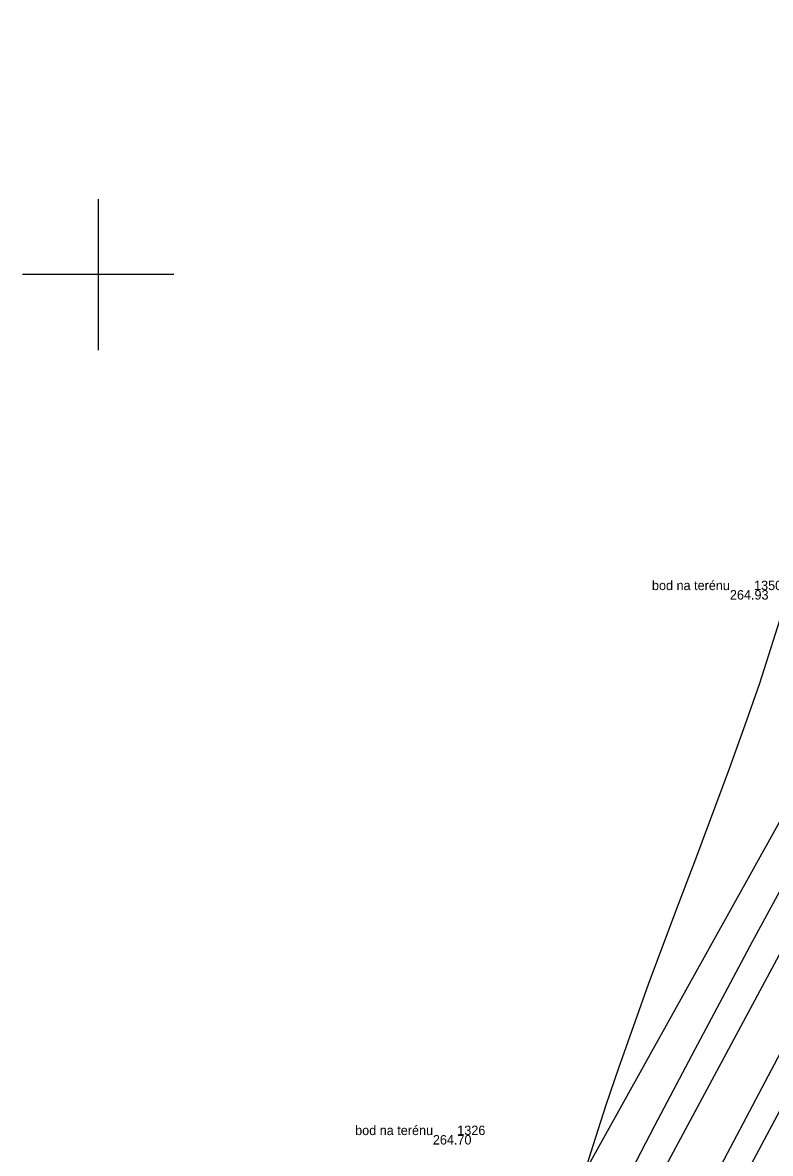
# Model space of a CAD drawing. Extents: x -567962 to -566460, y -1093720 to -1089838.
# Drawn here: x -567204 to -567164.4, y -1090846.6 to -1090786.7 of the extents above; entities that cross this region are included whole.
import ezdxf

# ---------------------------------------------------------------- set-up
doc = ezdxf.new("R2010")
doc.units = 0
for name, color, linetype in [('0_osa hráze', 7, 'Continuous'), ('bod_znacka', 7, 'Continuous'), ('cislo_bodu', 7, 'Continuous'), ('ctvercova_sit', 7, 'Continuous'), ('hlavni_vrst', 7, 'Continuous'), ('hrana_L', 7, 'Continuous'), ('kod_bodu', 7, 'Continuous'), ('norm_vrst', 7, 'Continuous'), ('vyska_bodu', 7, 'Continuous')]:
    doc.layers.add(name, color=color, linetype=linetype)

msp = doc.modelspace()

# ---------------------------------------------------------------- linework, layer by layer
at = {"layer": '0_osa hráze'}
msp.add_lwpolyline([(-567089.84, -1090700.38), (-567096.414, -1090713.39), (-567177.884, -1090867.779)], dxfattribs=at)
at = {"layer": 'bod_znacka'}
for p, q in [((-567165.26, -1090816.72), (-567165.26, -1090816.72)), ((-567180.98, -1090845.59), (-567180.98, -1090845.59))]:
    msp.add_line(p, q, dxfattribs=at)
at = {"layer": 'ctvercova_sit'}
for points in [[(-567200, -1090796), (-567200, -1090804)], [(-567196, -1090800), (-567204, -1090800)]]:
    msp.add_lwpolyline(points, dxfattribs=at)
at = {"layer": 'hlavni_vrst'}
msp.add_lwpolyline([(-567162.493, -1090812.221), (-567162.528, -1090812.45), (-567163.012, -1090814.932), (-567163.353, -1090816.337), (-567163.66, -1090817.553), (-567164.977, -1090821.675), (-567165.662, -1090823.624), (-567166.58, -1090826.191), (-567167.297, -1090828.123), (-567168.37, -1090830.969), (-567169.425, -1090833.739), (-567170.866, -1090837.606), (-567171.566, -1090839.547), (-567172.449, -1090842.05), (-567173.114, -1090844.011), (-567173.801, -1090846.164), (-567174.216, -1090847.494)], dxfattribs=at)
at = {"layer": 'hrana_L'}
for p, q in [((-567159.04, -1090820.21), (-567174.87, -1090848.67)), ((-567156.18, -1090821.59), (-567171.65, -1090850.41)), ((-567168.28, -1090852.53), (-567152.75, -1090823.34))]:
    msp.add_line(p, q, dxfattribs=at)
at = {"layer": 'norm_vrst'}
msp.add_lwpolyline([(-567162.51, -1090830.095), (-567165.357, -1090835.349), (-567168.398, -1090841.051), (-567170.527, -1090845.095), (-567172.703, -1090849.28)], dxfattribs=at)

# ---------------------------------------------------------------- texts
at = {"layer": 'cislo_bodu'}
for s, p in [('1350', (-567165.26, -1090816.72)), ('1326', (-567180.98, -1090845.59))]:
    msp.add_text(s, height=0.5, dxfattribs=at).set_placement(p)
at = {"layer": 'kod_bodu'}
for p in [(-567170.669, -1090816.72), (-567186.389, -1090845.59)]:
    msp.add_text('bod na terénu', height=0.5, dxfattribs=at).set_placement(p)
at = {"layer": 'vyska_bodu'}
for s, p in [('264.93', (-567166.541, -1090817.22)), ('264.70', (-567182.273, -1090846.09))]:
    msp.add_text(s, height=0.5, dxfattribs=at).set_placement(p)

doc.saveas('drawing.dxf')
